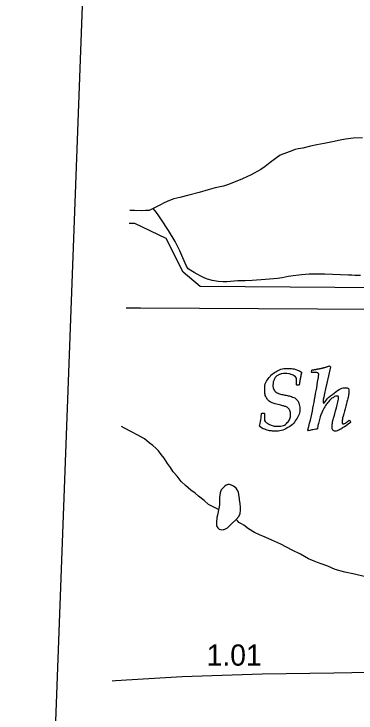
# Model space of a CAD drawing. Extents: x 2169602 to 2449496, y 721995 to 810662.
# Drawn here: x 2169994.4 to 2170042.4, y 724766 to 724863.9 of the extents above; entities that cross this region are included whole.
import ezdxf

# ---------------------------------------------------------------- set-up
doc = ezdxf.new("R2010")
doc.units = 0
doc.layers.add('Old_Level_1', color=7, linetype='Continuous')

msp = doc.modelspace()

# ---------------------------------------------------------------- linework, layer by layer
at = {"layer": 'Old_Level_1'}
msp.add_lwpolyline([(2170008.611, 724987.872), (2170579.909, 724966.498), (2170563.125, 724517.904), (2169991.828, 724539.278)], close=True, dxfattribs=at)
for points in [[(2170043.249, 724846.57), (2170041.977, 724846.511), (2170040.881, 724846.408), (2170040.13, 724846.262), (2170039.039, 724846.022), (2170037.898, 724845.769), (2170036.856, 724845.581), (2170035.993, 724845.383), (2170034.901, 724845.143), (2170034.239, 724845.041), (2170033.82, 724844.94), (2170033.006, 724844.61), (2170032.63, 724844.465), (2170031.724, 724844.13), (2170030.306, 724843.12), (2170029.599, 724842.541), (2170029.024, 724842.117), (2170027.65, 724841.39), (2170026.427, 724840.815), (2170024.478, 724840.048), (2170023.771, 724839.808), (2170022.631, 724839.556), (2170021.632, 724839.273), (2170020.394, 724838.93), (2170018.927, 724838.545), (2170017.645, 724838.199), (2170016.836, 724838.003), (2170015.979, 724837.718), (2170015.375, 724837.424), (2170015.043, 724837.233), (2170014.322, 724836.85), (2170013.947, 724836.657)], [(2170013.947, 724836.657), (2170013.571, 724836.473), (2170013.381, 724836.375), (2170012.855, 724836.368), (2170012.295, 724836.319), (2170011.286, 724836.403), (2170010.632, 724836.405)], [(2170042.986, 724827.272), (2170042.177, 724827.27), (2170041.753, 724827.315), (2170041.324, 724827.311), (2170037.952, 724827.484), (2170036.807, 724827.474), (2170035.808, 724827.471), (2170034.76, 724827.368), (2170033.917, 724827.265), (2170032.86, 724827.126), (2170032.016, 724826.973), (2170031.344, 724826.874), (2170029.682, 724826.719), (2170027.791, 724826.571), (2170026.831, 724826.514), (2170025.789, 724826.508), (2170024.229, 724826.407), (2170023.752, 724826.402), (2170023.045, 724826.451), (2170022.178, 724826.582), (2170021.417, 724826.822), (2170021.076, 724826.96), (2170020.613, 724827.194), (2170020.082, 724827.477), (2170019.658, 724827.714), (2170019.219, 724827.993), (2170018.844, 724828.233), (2170018.605, 724828.607), (2170018.079, 724829.746), (2170017.645, 724830.737), (2170017.022, 724832.066), (2170016.062, 724833.58), (2170015.004, 724835.243), (2170014.517, 724835.905), (2170014.195, 724836.33), (2170013.947, 724836.657)], [(2170085.334, 724811.477), (2170079.774, 724814.008), (2170070.646, 724816.924), (2170063.897, 724817.684), (2170059.545, 724819.256), (2170054.769, 724824.967), (2170051.992, 724825.491), (2170020.501, 724825.744), (2170018.123, 724827.741), (2170015.725, 724832.468), (2170011.349, 724834.584), (2170010.562, 724834.544)], [(2170094.221, 724816.569), (2170093.102, 724816.519), (2170090.914, 724817.788), (2170084.933, 724821.123), (2170082.446, 724821.869), (2170080.805, 724822.118), (2170076.627, 724822.118), (2170045.219, 724822.516), (2170012.169, 724822.716), (2170010.12, 724822.722)], [(2170038.628, 724814.605), (2170038.776, 724814.474)], [(2170034.694, 724813.721), (2170034.718, 724813.655)], [(2170036.17, 724813.685), (2170036.117, 724813.738), (2170036.158, 724813.994), (2170036.212, 724814.047)], [(2170034.023, 724812.26), (2170034.011, 724812.872)], [(2170036.978, 724812.379), (2170037.079, 724813.002)], [(2170034.403, 724811.934), (2170034.344, 724811.886), (2170034.059, 724811.886), (2170034.011, 724811.94)], [(2170029.126, 724807.951), (2170029.191, 724808.004), (2170029.47, 724808.004), (2170029.517, 724807.956), (2170029.506, 724807.292)], [(2170041.406, 724806.983), (2170041.477, 724806.977), (2170041.602, 724806.769), (2170041.584, 724806.686)], [(2170023.069, 724794.471), (2170022.499, 724794.75), (2170021.69, 724795.171), (2170021.071, 724795.738), (2170020.301, 724796.355), (2170019.829, 724796.783), (2170019.205, 724797.206), (2170018.445, 724797.87), (2170017.87, 724798.429), (2170017.304, 724799.141), (2170016.72, 724799.759), (2170016.335, 724800.367), (2170015.954, 724800.936), (2170015.467, 724801.655), (2170015.053, 724802.171), (2170014.663, 724802.693), (2170014.283, 724803.068), (2170013.898, 724803.445), (2170013.377, 724803.822), (2170012.704, 724804.387), (2170011.798, 724804.909), (2170010.886, 724805.374), (2170009.892, 724805.891), (2170009.498, 724806.094)], [(2170028.852, 724806.104), (2170028.829, 724806.176)], [(2170035.707, 724805.517), (2170035.589, 724805.629)], [(2170025.55, 724793.104), (2170025.925, 724793.49), (2170026.12, 724793.914), (2170026.169, 724794.388), (2170026.159, 724794.775), (2170026.115, 724795.342), (2170026.013, 724795.819), (2170026.013, 724796.002), (2170025.915, 724796.576), (2170025.862, 724796.912), (2170025.715, 724797.243), (2170025.569, 724797.476), (2170025.194, 724797.755), (2170024.906, 724797.905), (2170024.619, 724797.996), (2170024.424, 724797.996), (2170024.146, 724797.894), (2170023.912, 724797.708), (2170023.717, 724797.515), (2170023.44, 724797.23), (2170023.298, 724796.799), (2170023.206, 724796.186), (2170023.206, 724795.655), (2170023.211, 724795.183), (2170023.128, 724794.568), (2170023.069, 724794.471)], [(2170023.069, 724794.471), (2170023.025, 724794.14), (2170022.933, 724793.71), (2170022.84, 724793.378), (2170022.835, 724793.185), (2170022.792, 724792.855), (2170022.796, 724792.469), (2170022.801, 724792.237), (2170022.845, 724792.095), (2170022.996, 724791.899), (2170023.177, 724791.717), (2170023.371, 724791.668), (2170023.566, 724791.62), (2170023.756, 724791.668), (2170023.898, 724791.676), (2170024.083, 724791.763), (2170024.322, 724791.911), (2170024.892, 724792.48), (2170025.55, 724793.104)], [(2170043.507, 724785.086), (2170042.123, 724785.41), (2170040.798, 724785.688), (2170039.424, 724786.098), (2170038.415, 724786.531), (2170037.47, 724786.857), (2170036.943, 724787.043), (2170036.471, 724787.23), (2170035.705, 724787.557), (2170034.551, 724788.213), (2170033.415, 724788.781), (2170031.797, 724789.623), (2170030.559, 724790.187), (2170029.609, 724790.61), (2170028.844, 724790.937), (2170028.123, 724791.268), (2170027.309, 724791.787), (2170026.646, 724792.301), (2170026.305, 724792.497), (2170025.935, 724792.678), (2170025.789, 724792.826), (2170025.55, 724793.104)], [(2170008.166, 724770.483), (2170008.65, 724770.53), (2170018.001, 724771.078), (2170029.191, 724771.476), (2170039.238, 724771.576), (2170051.759, 724771.849), (2170061.495, 724771.924)]]:
    msp.add_lwpolyline(points, dxfattribs=at)
for points, degree in [([(2170036.212, 724814.047), (2170037.494, 724814.207), (2170038.628, 724814.605)], 2), ([(2170038.776, 724814.474), (2170037.916, 724810.824), (2170037.494, 724808.776), (2170038.307, 724810.064), (2170039.284, 724810.797), (2170040.261, 724811.53), (2170040.872, 724811.53), (2170041.365, 724811.53), (2170041.365, 724811.014), (2170041.365, 724810.729), (2170041.284, 724810.369), (2170041.204, 724810.01), (2170040.824, 724808.633), (2170040.409, 724807.125), (2170040.409, 724806.763), (2170040.409, 724806.502), (2170040.575, 724806.502), (2170040.688, 724806.502), (2170040.848, 724806.597), (2170041.008, 724806.692), (2170041.406, 724806.983)], 3), ([(2170034.011, 724812.872), (2170033.803, 724813.186), (2170033.367, 724813.367), (2170032.931, 724813.548), (2170032.432, 724813.548), (2170031.951, 724813.548), (2170031.548, 724813.361), (2170031.144, 724813.175), (2170030.93, 724812.774), (2170030.716, 724812.373), (2170030.716, 724811.898), (2170030.716, 724811.53), (2170030.847, 724811.293), (2170030.978, 724811.055), (2170031.185, 724810.916), (2170031.393, 724810.776), (2170031.634, 724810.696), (2170031.874, 724810.616), (2170032.557, 724810.485), (2170033.162, 724810.367), (2170033.474, 724810.248), (2170033.786, 724810.129), (2170033.999, 724809.921), (2170034.213, 724809.714), (2170034.341, 724809.378), (2170034.468, 724809.043), (2170034.468, 724808.633), (2170034.468, 724807.832), (2170033.973, 724807.09), (2170033.477, 724806.348), (2170032.702, 724805.911), (2170031.927, 724805.475), (2170030.96, 724805.475), (2170030.36, 724805.475), (2170029.793, 724805.647), (2170029.226, 724805.819), (2170028.852, 724806.104)], 3), ([(2170029.506, 724807.292), (2170029.506, 724807.208), (2170029.517, 724806.953), (2170029.684, 724806.674), (2170030.215, 724806.413), (2170030.746, 724806.152), (2170031.346, 724806.152), (2170032.26, 724806.152), (2170032.714, 724806.662), (2170033.168, 724807.173), (2170033.168, 724807.82), (2170033.168, 724808.111), (2170033.07, 724808.342), (2170032.972, 724808.574), (2170032.83, 724808.701), (2170032.687, 724808.829), (2170032.497, 724808.9), (2170032.307, 724808.972), (2170031.904, 724809.067), (2170030.942, 724809.298), (2170030.512, 724809.488), (2170030.081, 724809.678), (2170029.82, 724810.114), (2170029.559, 724810.551), (2170029.559, 724811.215), (2170029.559, 724812.118), (2170030.052, 724812.806), (2170030.544, 724813.495), (2170031.28, 724813.872), (2170032.017, 724814.249), (2170032.865, 724814.249), (2170033.928, 724814.249), (2170034.694, 724813.721)], 3), ([(2170034.718, 724813.655), (2170034.51, 724812.806), (2170034.403, 724811.934)], 2), ([(2170037.079, 724813.002), (2170037.126, 724813.269), (2170037.126, 724813.376), (2170037.126, 724813.513), (2170037.049, 724813.59), (2170036.972, 724813.667), (2170036.77, 724813.673), (2170036.568, 724813.679), (2170036.17, 724813.685)], 3), ([(2170034.011, 724811.94), (2170034.023, 724812.153), (2170034.023, 724812.26)], 2), ([(2170035.589, 724805.629), (2170035.98, 724806.923), (2170036.393, 724809.09), (2170036.806, 724811.257), (2170036.978, 724812.379)], 3), ([(2170041.584, 724806.686), (2170040.575, 724805.926), (2170040.13, 724805.701), (2170039.685, 724805.475), (2170039.418, 724805.475), (2170039.245, 724805.475), (2170039.118, 724805.617), (2170038.99, 724805.76), (2170038.99, 724806.086), (2170038.99, 724806.312), (2170039.041, 724806.576), (2170039.091, 724806.84), (2170039.317, 724807.677), (2170039.892, 724809.826), (2170039.892, 724810.123), (2170039.892, 724810.39), (2170039.667, 724810.39), (2170039.489, 724810.39), (2170039.21, 724810.218), (2170038.765, 724809.939), (2170038.307, 724809.34), (2170037.85, 724808.74), (2170037.536, 724808.01), (2170037.334, 724807.529), (2170037.108, 724806.656), (2170036.966, 724806.092), (2170036.966, 724805.754), (2170036.782, 724805.754), (2170036.351, 724805.665), (2170035.921, 724805.576), (2170035.707, 724805.517)], 3), ([(2170028.829, 724806.176), (2170028.882, 724806.359), (2170028.998, 724807.06), (2170029.114, 724807.761), (2170029.126, 724807.951)], 3)]:
    msp.add_open_spline(points, degree=degree, dxfattribs=at)

# ---------------------------------------------------------------- texts
msp.add_text('1.01', height=2.9707, rotation=0.02, dxfattribs=at).set_placement((2170021.411, 724772.595))

doc.saveas('drawing.dxf')
